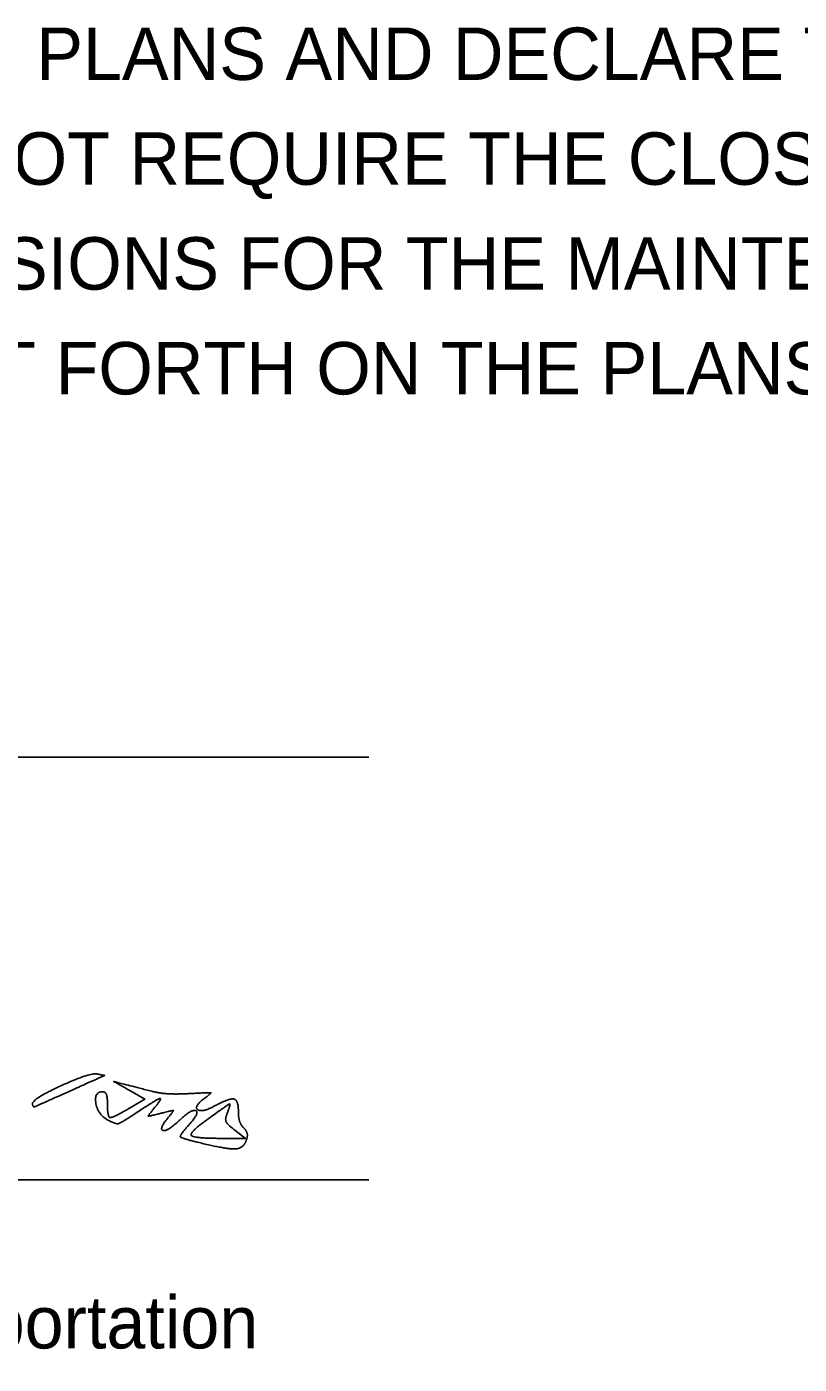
# Model space of a CAD drawing. Extents: x -1.1 to 34, y 0 to 29.8.
# Drawn here: x 27.241 to 29.305, y 6.685 to 10.258 of the extents above; entities that cross this region are included whole.
import ezdxf

# ---------------------------------------------------------------- set-up
doc = ezdxf.new("R2010")
doc.units = 0
doc.layers.add('SH_Data', color=7, linetype='Continuous')
doc.layers.add('SH_Text', color=7, linetype='Continuous')

msp = doc.modelspace()

# ---------------------------------------------------------------- linework, layer by layer
at = {"layer": 'SH_Data'}
for p, q in [((24.6551, 8.3067), (28.1551, 8.3067)), ((24.6551, 7.1773), (28.1551, 7.1773))]:
    msp.add_line(p, q, dxfattribs=at)
at = {"layer": 'SH_Text'}
for p, q in [((27.2566, 7.3815), (27.2566, 7.3815)), ((27.7091, 7.2753), (27.7091, 7.2753))]:
    msp.add_line(p, q, dxfattribs=at)
for points in [[(27.5204, 7.3719), (27.5568, 7.3934), (27.5161, 7.4164)], [(27.7691, 7.2884), (27.8254, 7.2885), (27.7967, 7.3106)]]:
    msp.add_lwpolyline(points, dxfattribs=at)
for points in [[(27.2566, 7.3815), (27.2566, 7.3939), (27.4095, 7.4642), (27.4284, 7.4605)], [(27.4284, 7.4605), (27.4491, 7.4565), (27.4498, 7.4569), (27.3282, 7.4023)], [(27.5161, 7.4164), (27.4733, 7.4405), (27.4723, 7.4405), (27.5754, 7.4141)], [(27.3282, 7.4023), (27.2656, 7.3742), (27.2566, 7.3716), (27.2566, 7.3815)], [(27.4577, 7.3374), (27.4312, 7.3516), (27.4202, 7.4129), (27.4441, 7.4129)], [(27.4441, 7.4129), (27.451, 7.4129), (27.4566, 7.3989), (27.4566, 7.3817)], [(27.5754, 7.4141), (27.596, 7.4089), (27.641, 7.4061), (27.6754, 7.408)], [(27.6754, 7.408), (27.7303, 7.4111), (27.7351, 7.4095), (27.7153, 7.3947)], [(27.4566, 7.3817), (27.4566, 7.3449), (27.4709, 7.3427), (27.5204, 7.3719)], [(27.58, 7.3671), (27.6044, 7.3967), (27.5887, 7.3929), (27.5324, 7.3557)], [(27.5994, 7.3554), (27.5664, 7.3472), (27.5645, 7.3483), (27.58, 7.3671)], [(27.6195, 7.3447), (27.6341, 7.3623), (27.6319, 7.3635), (27.5994, 7.3554)], [(27.6734, 7.3233), (27.7039, 7.3569), (27.6822, 7.3679), (27.6482, 7.3359)], [(27.7153, 7.3947), (27.6864, 7.3732), (27.7094, 7.3568), (27.7431, 7.3749)], [(27.7769, 7.3561), (27.7868, 7.3819), (27.7786, 7.3788), (27.716, 7.3332)], [(27.7431, 7.3749), (27.7833, 7.3964), (27.8066, 7.3906), (27.8066, 7.3592)], [(27.5324, 7.3557), (27.4923, 7.3292), (27.4791, 7.3259), (27.4577, 7.3374)], [(27.6482, 7.3359), (27.6163, 7.306), (27.5933, 7.313), (27.6195, 7.3447)], [(27.716, 7.3332), (27.6733, 7.3022), (27.6897, 7.2883), (27.7691, 7.2884)], [(27.7967, 7.3106), (27.7763, 7.3263), (27.7705, 7.3395), (27.7769, 7.3561)], [(27.8066, 7.3592), (27.8066, 7.3434), (27.813, 7.3241), (27.8208, 7.3163)], [(27.7091, 7.2753), (27.6544, 7.2882), (27.6487, 7.2959), (27.6734, 7.3233)], [(27.8208, 7.3163), (27.8286, 7.3085), (27.8316, 7.2933), (27.8274, 7.2825)], [(27.8274, 7.2825), (27.8194, 7.2614), (27.7782, 7.2589), (27.7091, 7.2753)]]:
    msp.add_open_spline(points, degree=2, dxfattribs=at)

# ---------------------------------------------------------------- texts
at = {"layer": 'SH_Data'}
for s, p in [(' I HEREBY APPROVE THESE PLANS AND DECLARE THAT THE MAKING OF', (24.6551, 10.1155)), ('THIS IMPROVEMENT WILL NOT REQUIRE THE CLOSING TO TRAFFIC OF THE', (24.6551, 9.8355)), ('HIGHWAY AND THAT PROVISIONS FOR THE MAINTENANCE AND SAFETY', (24.6551, 9.5555)), ('OF TRAFFIC WILL BE AS SET FORTH ON THE PLANS AND ESTIMATES.', (24.6551, 9.2755))]:
    msp.add_text(s, height=0.14, dxfattribs=at).set_placement(p)
at = {"layer": 'SH_Text'}
msp.add_text('Director, Department of Transportation', height=0.14, dxfattribs=at).set_placement((24.6551, 6.7273))

doc.saveas('drawing.dxf')
